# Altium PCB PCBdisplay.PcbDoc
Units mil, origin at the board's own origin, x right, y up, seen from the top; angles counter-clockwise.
Board outline 2410 x 2530 mil, 2 copper layers (Top Layer, Bottom Layer); 12 components, 75 nets, 67 pads, 14 vias.
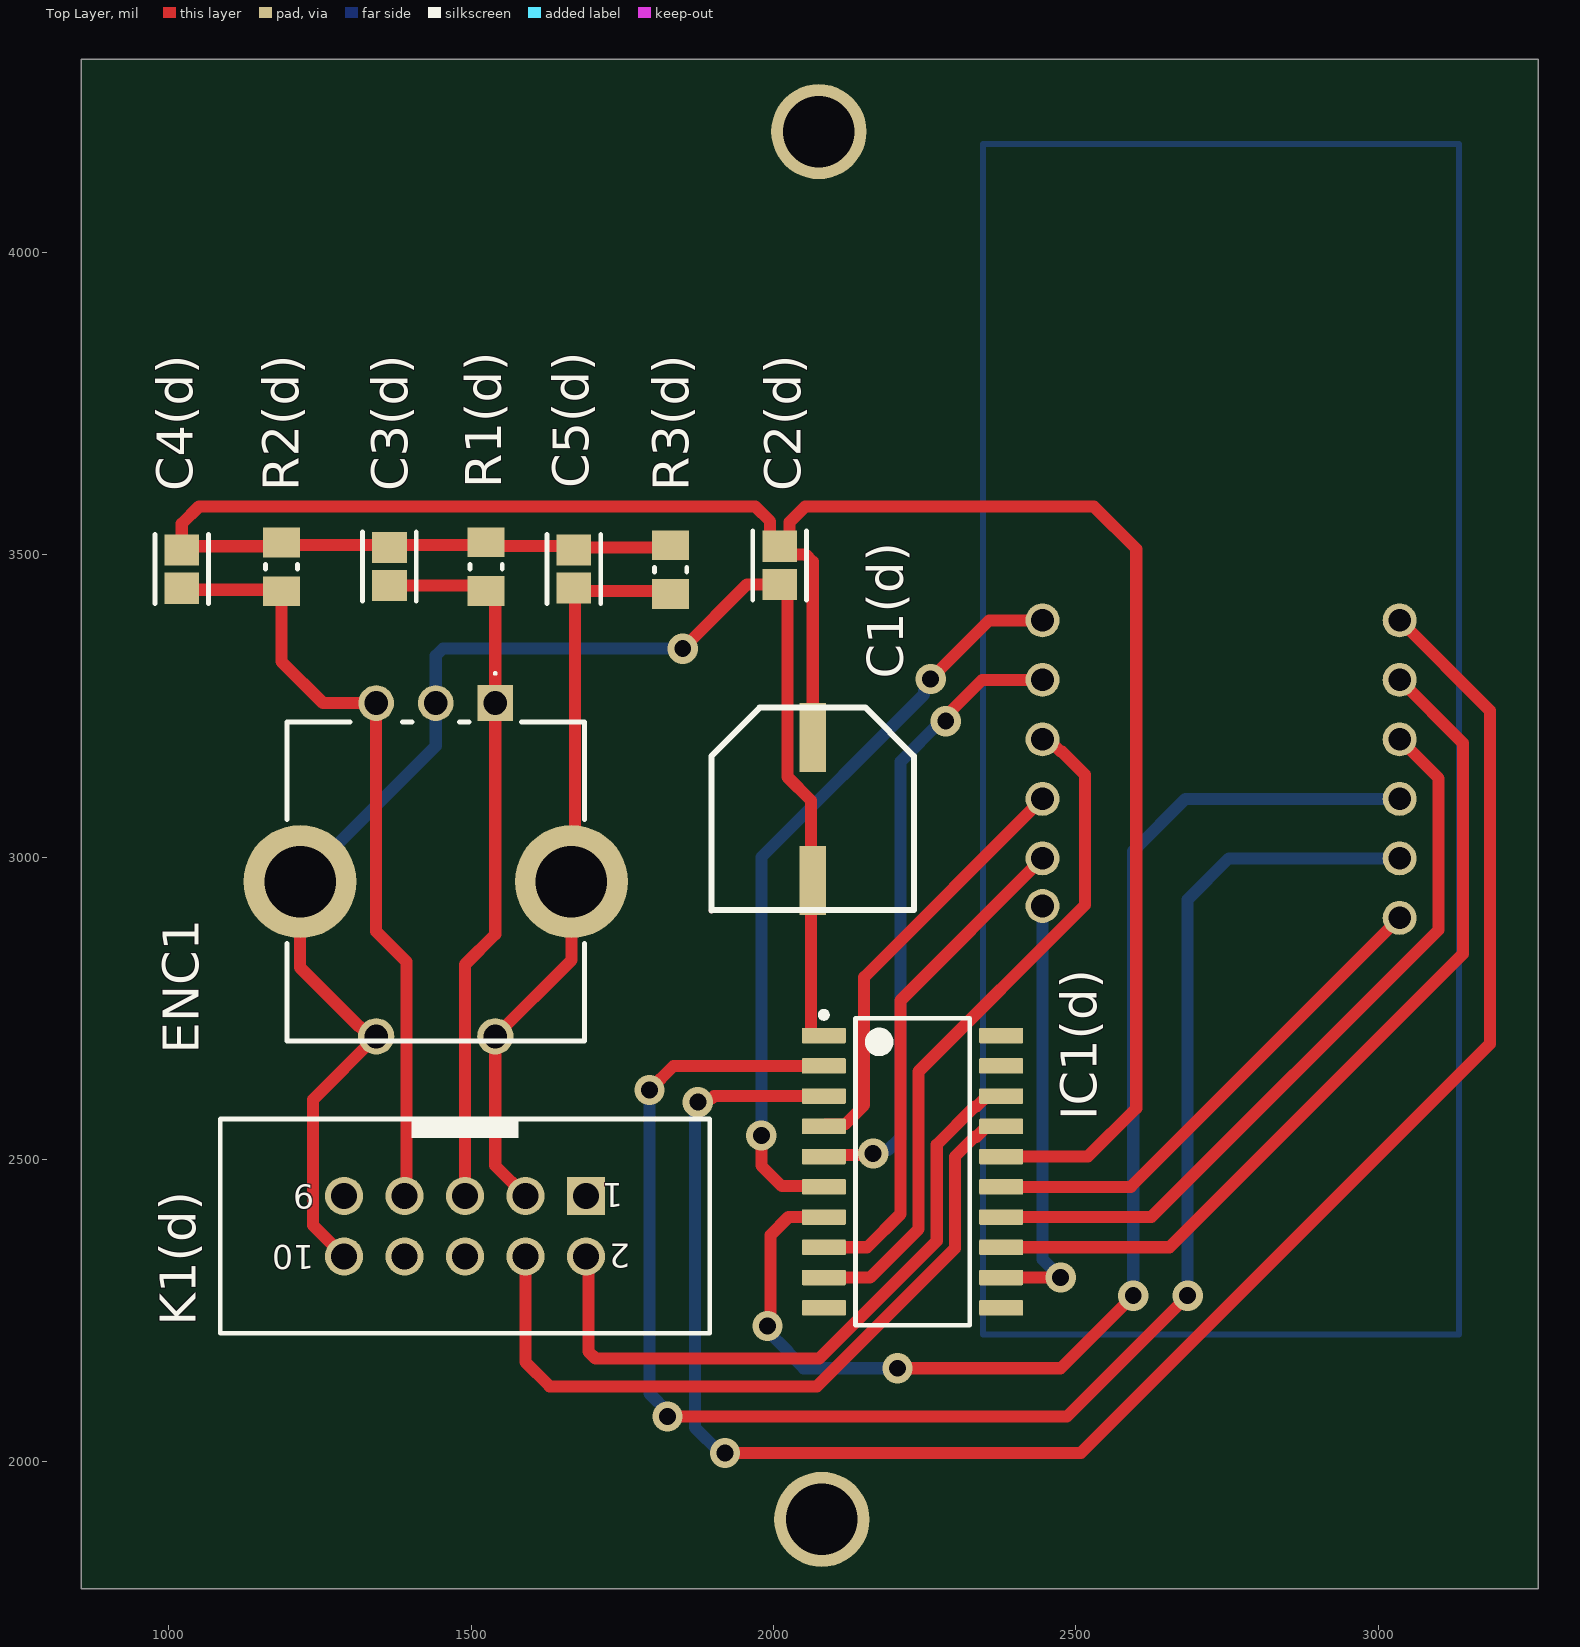
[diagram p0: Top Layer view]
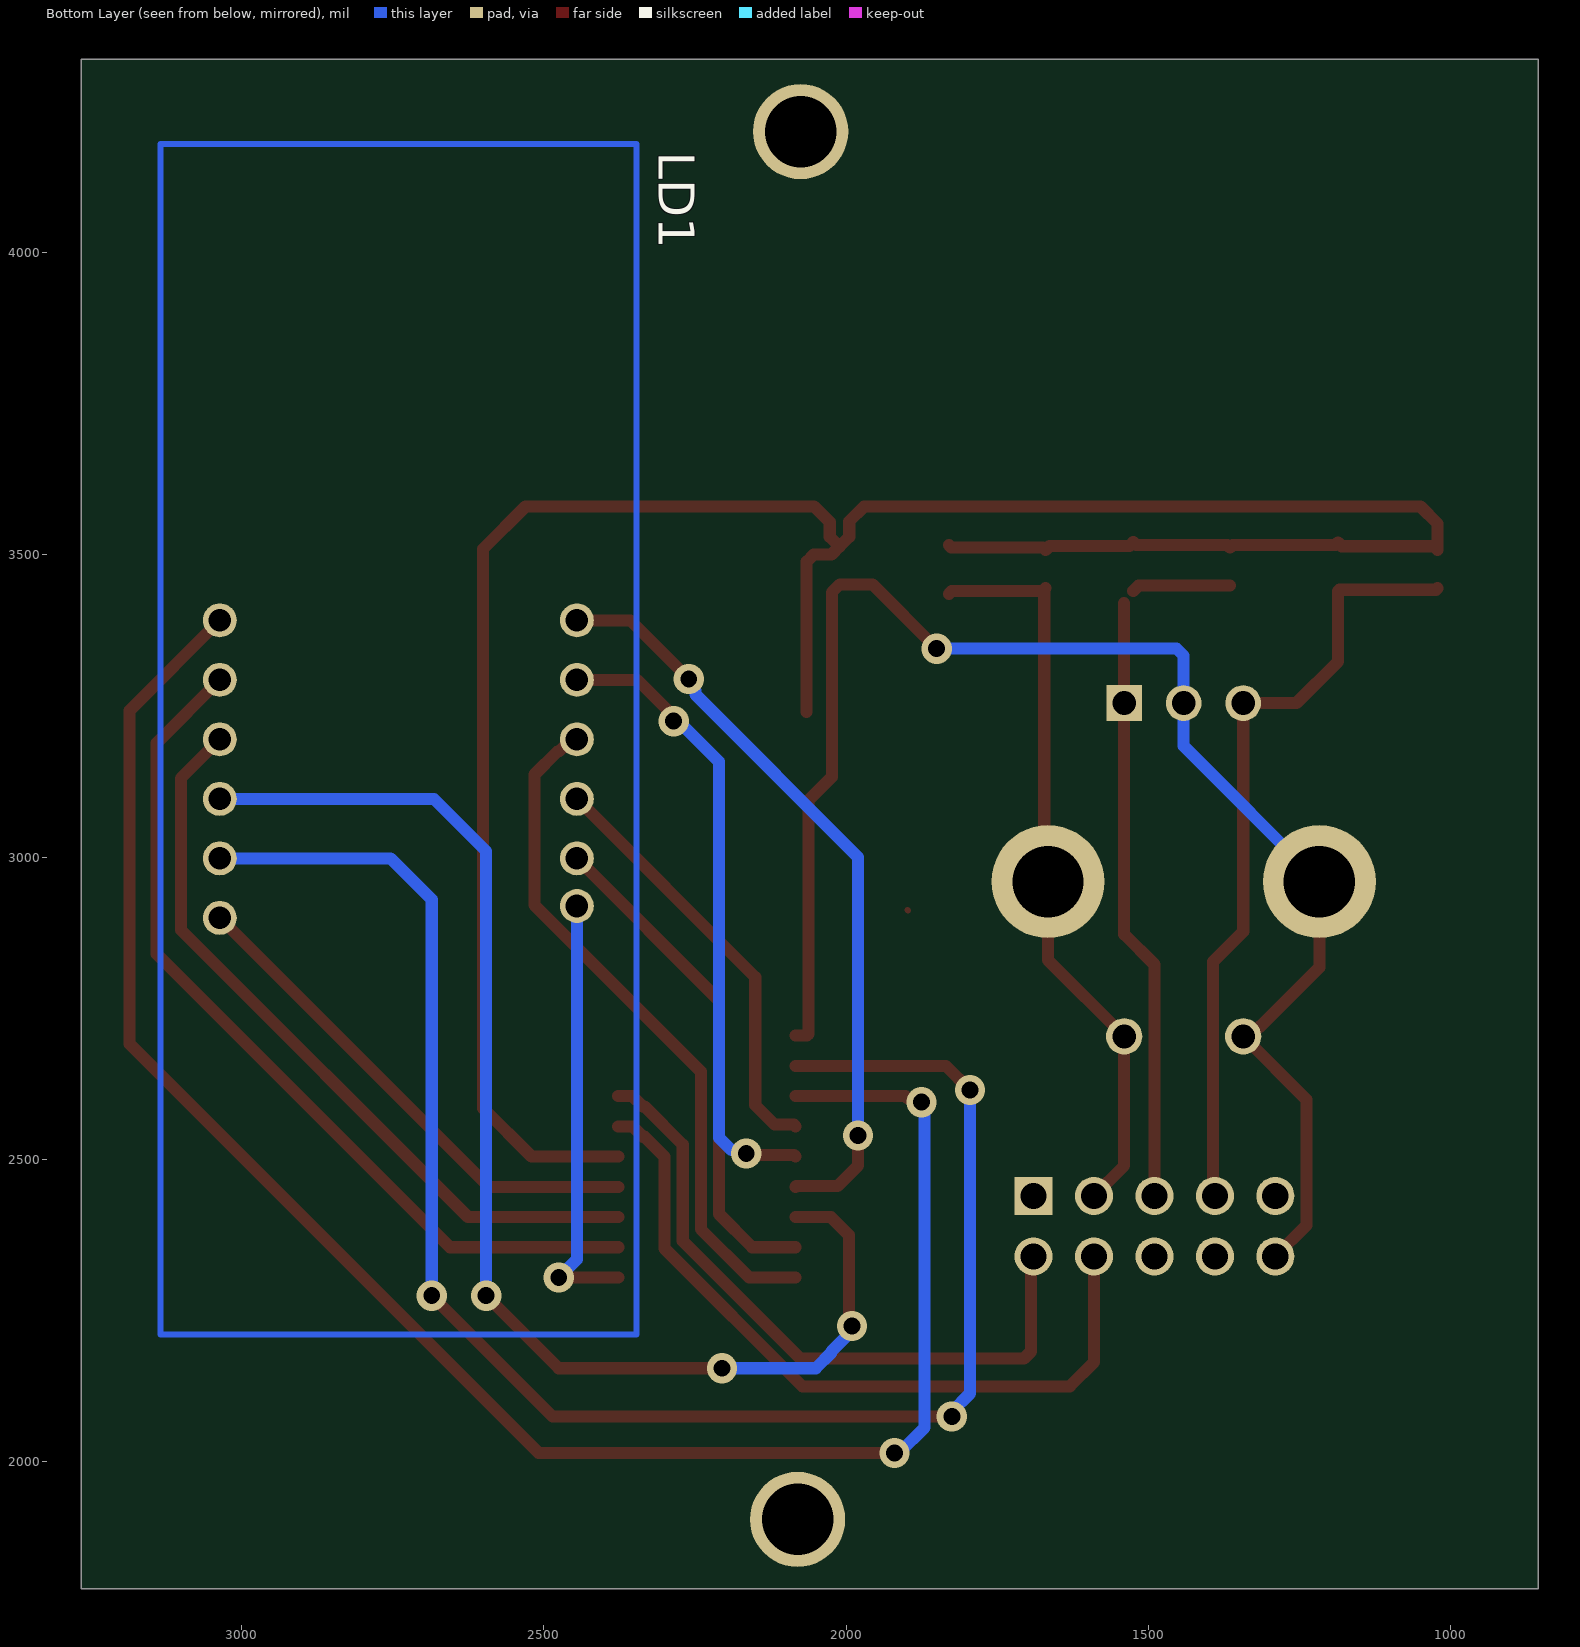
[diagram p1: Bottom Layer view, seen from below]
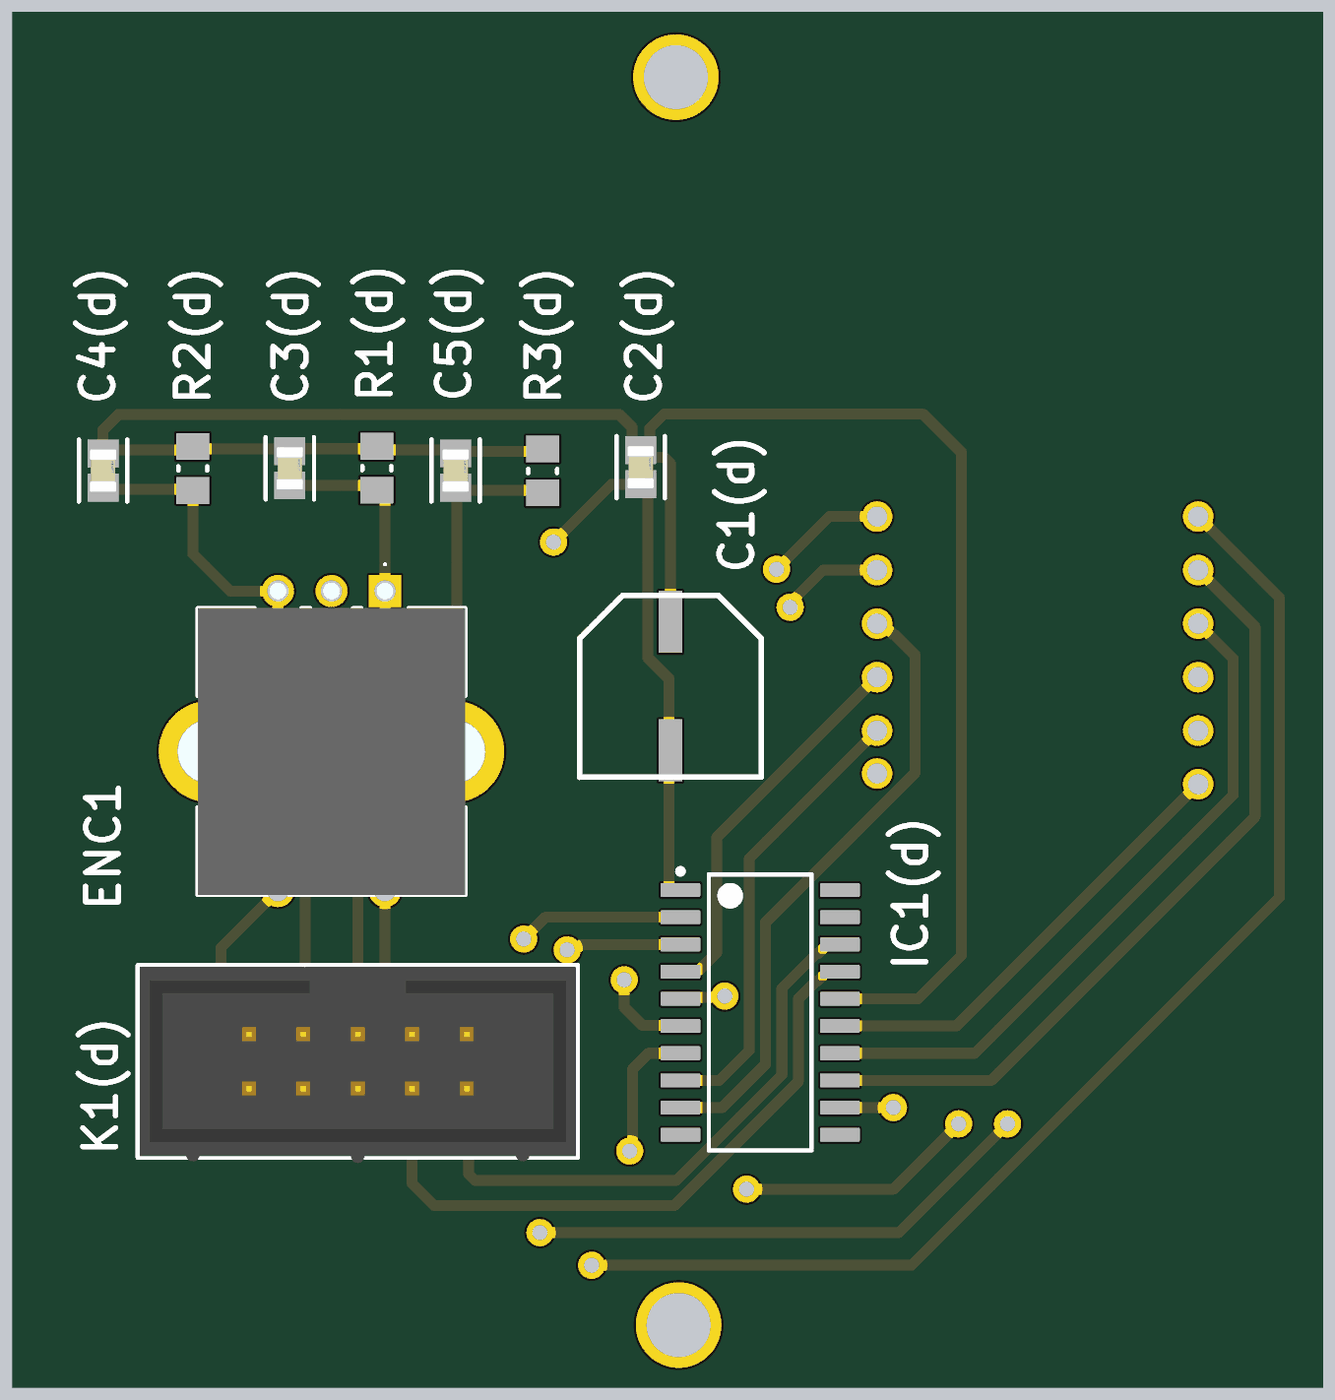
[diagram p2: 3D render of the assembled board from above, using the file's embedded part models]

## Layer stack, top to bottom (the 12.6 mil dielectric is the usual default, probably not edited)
Top Solder: solder mask 0.4, Solder Resist, Dk 3.5
Top Layer: signal copper 1.4
Dielectric 1: dielectric 12.6, FR-4, Dk 4.8
Bottom Layer: signal copper 1.4
Bottom Solder: solder mask 0.4, Solder Resist, Dk 3.5

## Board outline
855,4320 3265,4320 3265,1790 855,1790

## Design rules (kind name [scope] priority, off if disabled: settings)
Clearance [All] p1: gap=2 ignorepadtopadclearanceinfootprint=TRUE except(0: Arc-Hole Track-Hole SMDPad-Hole THPad-Hole Via-Hole Fill-Hole Poly-Hole Region-Hole Text-Hole)
Height [All] p1: minheight=0 maxheight=2000 prefheight=500
HoleSize [All] p1: absolutevalues=TRUE maxlimit=157.48 minlimit=0.98 maxpercent=80.000 minpercent=20.000
PolygonConnect [All] p1: connectstyle=Relief reliefconductorwidth=10 reliefentries=4 polygonreliefangle="90 Angle" airgapwidth=10
RoutingVias [All] p1: holewidth=28 width=50 viastyle="Through Hole" minholewidth=28 minwidth=50 maxholewidth=28 maxwidth=50
SilkToSolderMaskClearance [IsPad] p1: minsilkscreentomaskgap=0 clearancetoexposedcopper=TRUE
SolderMaskExpansion [All] p1: expansion=4 istentingtop=FALSE soldermaskfromhole=TRUE
Width [All] p1: maxlimit=26 minlimit=6 preferedwidth=20 minimp=50.000000 maximp=50.000000 favimp=50.000000
27 further rules are at their usual default settings.

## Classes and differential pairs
component class display: C1(d) C2(d) C3(d) C4(d) C5(d) ENC1 K1(d) R1(d) R2(d) R3(d)

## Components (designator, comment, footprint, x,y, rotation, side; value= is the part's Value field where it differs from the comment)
C1(d) "100µ" CE_D8_L10 2065,3080 r90 top
C2(d) "100n" "CC_0805_L (choke/capacitor)" 2010.25,3482.76 r270 top value="0.22 μF"
C3(d) "10n" "CC_0805_L (choke/capacitor)" 1365,3480.75 r270 top value="0.22 μF"
C4(d) "10n" "CC_0805_L (choke/capacitor)" 1021.53,3476.43 r270 top value="0.22 μF"
C5(d) "10n" "CC_0805_L (choke/capacitor)" 1669.92,3476.59 r270 top value="0.22 μF"
ENC1 "Rotary encoder" "PEC11R4225FN0024 (rotary enc)" 1540,3255 r180 top
IC1(d) "TM1637 LED Driver" "SOP_20_L (led driver)" 2230,2480 r0 top
K1(d) "61201021621" "box header 10-pin" 1490,2390 r180 top
LD1 "7 Sigment" 7-Segment 2445,3195 r0 bottom
R1(d) "10k" R_0805_L 1525,3480.75 r90 top
R2(d) "10k" R_0805_L 1186.53,3480.26 r90 top
R3(d) "10k" R_0805_L 1830,3475.75 r90 top

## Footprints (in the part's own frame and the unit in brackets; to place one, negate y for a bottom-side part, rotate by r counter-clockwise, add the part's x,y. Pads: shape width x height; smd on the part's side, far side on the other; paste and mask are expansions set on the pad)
7-Segment [mm]
  round 1.425 hole 0.95: 1(0,-5) 2(0,-2.5) 3(0,0) 4(0,2.5) 5(0,5) 6(0,7) 7(15,-5) 8(15,-2.5) 9(15,0) 10(15,2.5) 11(15,5) 12(15,7.5)
  Top Layer lines w0.254: -2.5,25 -2.5,15 -2.5,-25 17.5,-25 17.5,25 -2.5,25
"box header 10-pin" [mm] "10 pins, straight, gold plating"
  rect 1.6x1.6 hole 1.1: 1(-5.08,-1.27)
  round 1.6 hole 1.1: 2(-5.08,1.27) 3(-2.54,-1.27) 4(-2.54,1.27) 5(0,-1.27) 6(0,1.27) 7(2.54,-1.27) 8(2.54,1.27) 9(5.08,-1.27) 10(5.08,1.27)
  silkscreen extent -10.28,-4.5 10.28,4.5, body extent -10.18,-4.42 10.18,4.75, height 9.13
"CC_0805_L (choke/capacitor)" [mil]
  rect 51.36x57.33 smd paste+0 mask+0: 1(-31.53,0) 2(31.53,0)
  silkscreen extent -57,-44 57,44, body extent -67,-39 67,39, height 10
CE_D8_L10 [mm]
  rect 2.9x1.1 smd: 1(-3,0) 2(3,0)
  Top Layer lines w0.254: -4.259,4.25 -4.25,4.241
  silkscreen extent -4.26,-4.25 4.25,4.25
"PEC11R4225FN0024 (rotary enc)" [mm]
  round 4.74 hole 3: 1(-3.2,7.5) 2(8.2,7.5)
  round 1.524 hole 1: 1(0,14) 2(5,14)
  rect 1.5x1.5 hole 1: A1(0,0)
  round 1.5 hole 1: B1(5,0) C1(2.5,0)
  silkscreen extent -3.75,-1.3 8.75,14.2, body extent -4.67,-0.4 9.68,14.2, height 31.6
R_0805_L [mm] "Chip Resistor, 2-Leads, Body 2.00x1.25mm, IPC Low Density"
  rect 1.25x1.55 smd: 1(-1.025,0) 2(1.025,0)
  silkscreen extent -0.1,-0.67 0.1,0.68, body extent -1.1,-0.72 1.1,0.72, height 0.5
"SOP_20_L (led driver)" [mm] "SOIC,20-Leads,Body 12.9x5.6mm,Pitch 1.27mm,IPC Low Density"
  rrect15% 1.85x0.65 smd: 1(-3.725,5.715) 2(-3.725,4.445) 3(-3.725,3.175) 4(-3.725,1.905) 5(-3.725,0.635) 6(-3.725,-0.635) 7(-3.725,-1.905) 8(-3.725,-3.175) 9(-3.725,-4.445) 10(-3.725,-5.715) 11(3.725,-5.715) 12(3.725,-4.445) 13(3.725,-3.175) 14(3.725,-1.905) 15(3.725,-0.635) 16(3.725,0.635) 17(3.725,1.905) 18(3.725,3.175) 19(3.725,4.445) 20(3.725,5.715)
  silkscreen extent -3.85,-6.45 2.4,6.71, body extent -2.8,-6.45 2.8,6.45, height 2

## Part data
C1(d): library part "Capacitor (electrolytic)", Manufacturer=Panasonic, Max Operating Temperature="105 degC", Min Operating Temperature="-55 degC", Package Quantity=500, Voltage Rating="25 V"
C2(d) C3(d) C4(d) C5(d): library part "Capacitor (ceramic)", Capacitance="0.22 μF", Manufacturer=KEMET, Manufacturer Part Number=C0805C224K5RACTU, Package=C0805C-DN, Temperature="-55°C to +125°C", Temperature Characteristic=X7R, Temperature Coefficient=30ppm/°C, Temperature Range High=+125°C, Temperature Range Low=-55°C, Tolerance=0.1, Voltage Rating="50 V"
ENC1: Current Rating=10mA, Manufacturer=Bourns, Manufacturer Part Number=PEC11R-4015F-N0024, Package=0, Temperature="-30°C to +70°C", Temperature Range High=+70°C, Temperature Range Low=-30°C, Voltage Rating Dc=5V
IC1(d): library part "TM1637 LED Drive", Package=Package
K1(d): library part "Box Header", "Male Box Header WR-BHD, THT, Vertical, pitch 2.54 mm, 10 pins", Contact Resistance=20mOhm, Manufacturer="Wurth Elektronik", Operating Temperature=-40to125degC, Withstanding Voltage=500VAC, Working Voltage=250VAC
LD1: library part "4digit 7segment"
R1(d) R2(d) R3(d): library part Resistor, Manufacturer="Vishay Dale", Part Number=CRCW08050000Z0EA

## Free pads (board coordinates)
  round 157.48 hole 118.11: 6(2075,4200) 7(2080,1905)

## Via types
v1: diameter 50, hole 28, Top Layer to Bottom Layer, 14 vias

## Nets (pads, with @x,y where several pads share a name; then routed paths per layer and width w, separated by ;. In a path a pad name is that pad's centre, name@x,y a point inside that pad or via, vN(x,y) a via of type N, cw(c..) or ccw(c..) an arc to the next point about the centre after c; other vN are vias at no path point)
+5: K1(d).1
GND: C1(d).1 C2(d).2 ENC1.2 ENC1.C1 IC1(d).1 K1(d).10 | length 2615.1
  Top Layer w20: ENC1.2@1217.16,2959.72 1217.16,2817.84 1314.74,2720.26 1315.88,2720.26 1332.32,2703.82 1343.15,2703.82 1238.5,2599.17 1238.5,2391.5 1290,2340 ; v1(1850,3345) 1956.24,3451.24 2010.25,3451.24 2023.35,3438.14 2023.35,3132.74 2061.95,3094.14 2061.95,2707.8 2064.75,2705 2083.35,2705
  Bottom Layer w20: ENC1.2@1217.16,2959.72 1441.57,3184.13 ENC1.C1 1441.57,3333.28 1453.29,3345 v1(1850,3345)
NetB1_3: 
NetB1_4: 
NetB2_1: 
NetB2_3: 
NetC1(d)_2: C1(d).2 C2(d).1 C3(d).1 C4(d).1 C5(d).1 IC1(d).16 R1(d).2 R2(d).2 R3(d).2 | length 4071.7
  Top Layer w20: 1830,3516.1 1826.01,3512.11 1673.91,3512.11 1669.92,3508.12 1663.43,3514.61 1531.49,3514.61 1525,3521.1 1520.59,3516.69 1369.41,3516.69 1365,3512.28 1360.83,3516.44 1190.69,3516.44 1186.53,3520.61 1180.2,3514.28 1027.85,3514.28 1021.53,3507.96 1021.53,3551.53 1050,3580 1970,3580 1994.59,3555.41 1994.59,3529.95 2010.25,3514.29 ; 2065,3240 2065,3488.83 2053.28,3500.55 2023.99,3500.55 2010.25,3514.29 ; 2376.65,2505 2520,2505 2600,2585 2600,3510 2529.86,3580.14 2052.61,3580.14 2026.89,3554.42 2026.89,3529.97 2011.21,3514.29 2010.25,3514.29
NetC3(d)_2: C3(d).2 ENC1.A1 K1(d).5 R1(d).1 | length 1164.4
  Top Layer w20: 1365,3449.22 1516.17,3449.22 1525,3440.39 ; 1490,2440 1490,2822.67 1540,2872.67 ENC1.A1 1540,3420
NetC4(d)_2: C4(d).2 ENC1.B1 K1(d).7 R2(d).1 | length 1305.4
  Top Layer w20: 1021.53,3444.9 1024.03,3442.4 1184.03,3442.4 1186.53,3439.9 1186.53,3323.47 1255,3255 ENC1.B1 ; ENC1.B1@1343.02,3254.88 1343.02,2877.27 1393.15,2827.15 1393.15,2443.15 1390,2440
NetC5(d)_2: C5(d).2 ENC1.1 K1(d).3 R3(d).1 | length 1245.5
  Top Layer w20: 1590,2440 1540,2490 1540,2703.82 1665.98,2829.8 1665.98,2959.72 1672.16,2965.9 1672.16,3442.83 1669.92,3445.07 1674.76,3440.23 1825.16,3440.23 1830,3435.39
NetC7_2: 
NetC11_1: 
NetC13_2: 
NetC14_1: 
NetC14_2: 
NetD1: 
NetIC1(d)_2: IC1(d).2 LD1.11 | length 2843.2
  Top Layer w20: v1(1795,2615) 1835,2655 2083.35,2655 ; v1(1825,2075) 2485,2075 v1(2685,2275) ; LD1.11@3026.27,2998.15 LD1.11
  Bottom Layer w20: v1(1795,2615) 1795,2113.12 1825,2083.12 v1(1825,2075) ; v1(2685,2275) 2685,2930 2753.15,2998.15 LD1.11
NetIC1(d)_3: IC1(d).3 LD1.7 | length 3127.6
  Top Layer w20: v1(1875,2595) 1880.74,2600.74 1897.46,2600.74 1901.72,2605 2083.35,2605 ; v1(1920,2015) 2508.64,2015 3185,2691.36 3185,3242.4 LD1.7
  Bottom Layer w20: v1(1875,2595) 1870,2590 1870,2056.92 1911.92,2015 v1(1920,2015)
NetIC1(d)_4: IC1(d).4 LD1.4 | length 709.9
  Top Layer w20: 2083.35,2555 2086.14,2557.8 2117.8,2557.8 2150,2590 2150,2801.57 LD1.4
NetIC1(d)_5: IC1(d).5 LD1.2 | length 1057.3
  Top Layer w20: 2083.35,2505 2085.85,2507.5 2162.5,2507.5 v1(2165,2510) ; v1(2285,3225) 2285,3233.12 2345.31,3293.42 LD1.2
  Bottom Layer w20: v1(2165,2510) 2170.74,2515.74 2189.53,2515.74 2210,2536.21 2210,3158.12 2276.88,3225 v1(2285,3225)
NetIC1(d)_6: IC1(d).6 LD1.1 | length 1263.9
  Top Layer w20: v1(1980,2540) 1980,2490 2013.92,2456.08 2082.26,2456.08 2083.35,2455 ; v1(2260,3295) 2356.85,3391.85 LD1.1
  Bottom Layer w20: v1(1980,2540) 1980,3000 2249.04,3269.04 2249.04,3275.92 2260,3286.88 v1(2260,3295)
NetIC1(d)_7: IC1(d).7 LD1.10 | length 2158.3
  Top Layer w20: v1(1990,2225) 1995,2230 1995,2375 2025,2405 2083.35,2405 ; v1(2205,2155) 2475,2155 v1(2595,2275) ; LD1.10@3031.06,3096.57 LD1.10
  Bottom Layer w20: v1(1990,2225) 1990,2216.88 2024.02,2182.86 2024.02,2180.98 2050,2155 v1(2205,2155) ; v1(2595,2275) 2595,3010 2681.57,3096.57 LD1.10
NetIC1(d)_8: IC1(d).8 LD1.5 | length 834.9
  Top Layer w20: 2083.35,2355 2155,2355 2210,2410 2210,2763.15 LD1.5
NetIC1(d)_9: IC1(d).9 LD1.3 | length 1149.7
  Top Layer w20: 2083.35,2305 2160,2305 2240,2385 2240,2645.84 2515,2920.84 2515,3136.95 2477.33,3174.63 2475.14,3174.63 2454.77,3195 LD1.3
NetIC1(d)_12: IC1(d).12 LD1.6 | length 725.2
  Top Layer w20: 2376.65,2305 v1(2475,2305)
  Bottom Layer w20: LD1.6 2445,2335 v1(2475,2305)
NetIC1(d)_13: IC1(d).13 LD1.8 | length 1460.9
  Top Layer w20: 2376.65,2355 2655,2355 3140,2840 3140,3188.97 LD1.8
NetIC1(d)_14: IC1(d).14 LD1.9 | length 1261.8
  Top Layer w20: 2376.65,2405 2625,2405 3100,2880 3100,3130.55 LD1.9
NetIC1(d)_15: IC1(d).15 LD1.12 | length 843.1
  Top Layer w20: 2376.65,2455 2590.83,2455 LD1.12
NetIC1(d)_17: IC1(d).17 K1(d).4 | length 1245.3
  Top Layer w20: 1590,2340 1590,2165 1630,2125 2072.14,2125 2300,2352.86 2300,2504.72 2333.08,2537.8 2335.83,2537.8 2353.03,2555 2376.65,2555
NetIC1(d)_18: IC1(d).18 K1(d).2 | length 1119.5
  Top Layer w20: 1690,2340 1693.92,2336.08 1693.92,2182.79 1705.64,2171.08 2075.8,2171.08 2270,2365.28 2270,2524.72 2333.34,2588.06 2336.09,2588.06 2353.03,2605 2376.65,2605
NetIC2_1: 
NetIC2_2: 
NetIC2_6: 
NetIC2_7: 
NetIC3_1: 
NetIC3_2: 
NetIC3_3: 
NetIC3_11: 
NetIC3_16: 
NetIC3_17: 
NetIC3_23: 
NetIC3_24: 
NetIC3_25: 
NetIC3_26: 
NetIC3_27: 
NetIC3_31: 
NetIC3_32: 
NetIC3_33: 
NetIC3_34: 
NetIC3_35: 
NetIC3_38: 
NetIC3_39: 
NetIC3_41: 
NetIC3_44: 
NetIC3_45: 
NetIC3_46: 
NetIC3_47: 
NetIC3_48: 
NetK2_2: 
NetK3_2: 
NetK8_1: 
NetK8_2: 
NetL2_1: 
NetR7_2: 
NetR11_1: 
NetR17_1: 
NetR18_1: 
NetR18_2: 
NetR19_1: 
"PC0 CPU": 
"PD0 CPU": 
"PD1 CPU": 
"PD2 CPU": 
"PE0 CPU": 
VIN: 
pads on no net: IC1(d).10 IC1(d).11 IC1(d).19 IC1(d).20 K1(d).6 K1(d).8 K1(d).9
